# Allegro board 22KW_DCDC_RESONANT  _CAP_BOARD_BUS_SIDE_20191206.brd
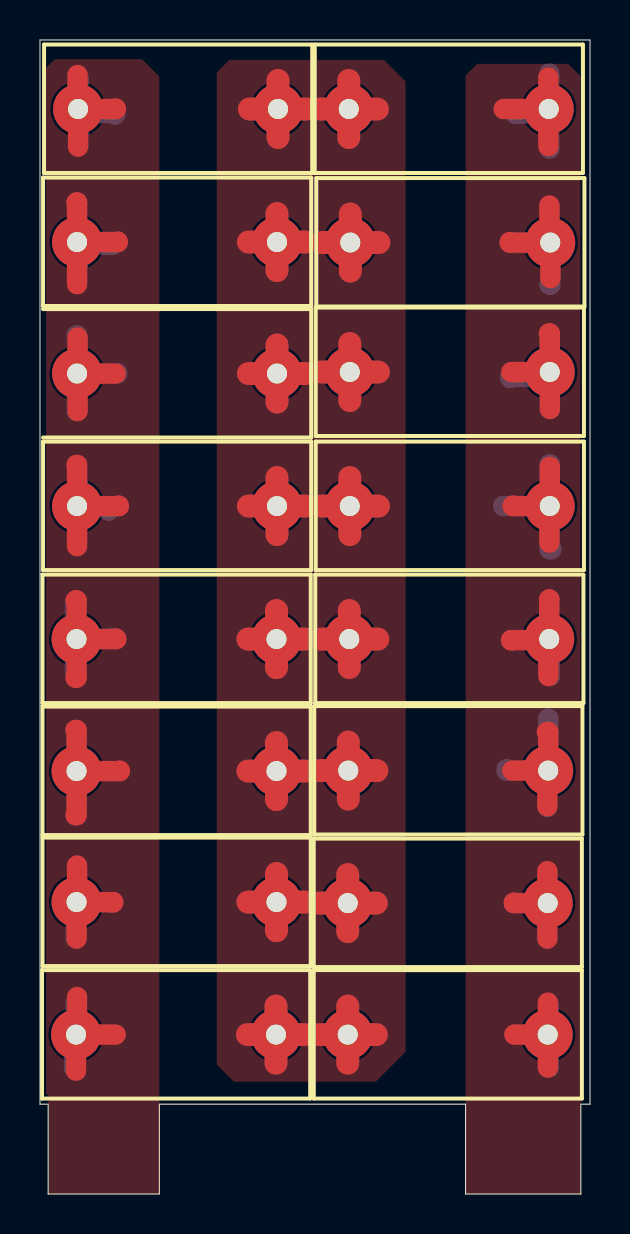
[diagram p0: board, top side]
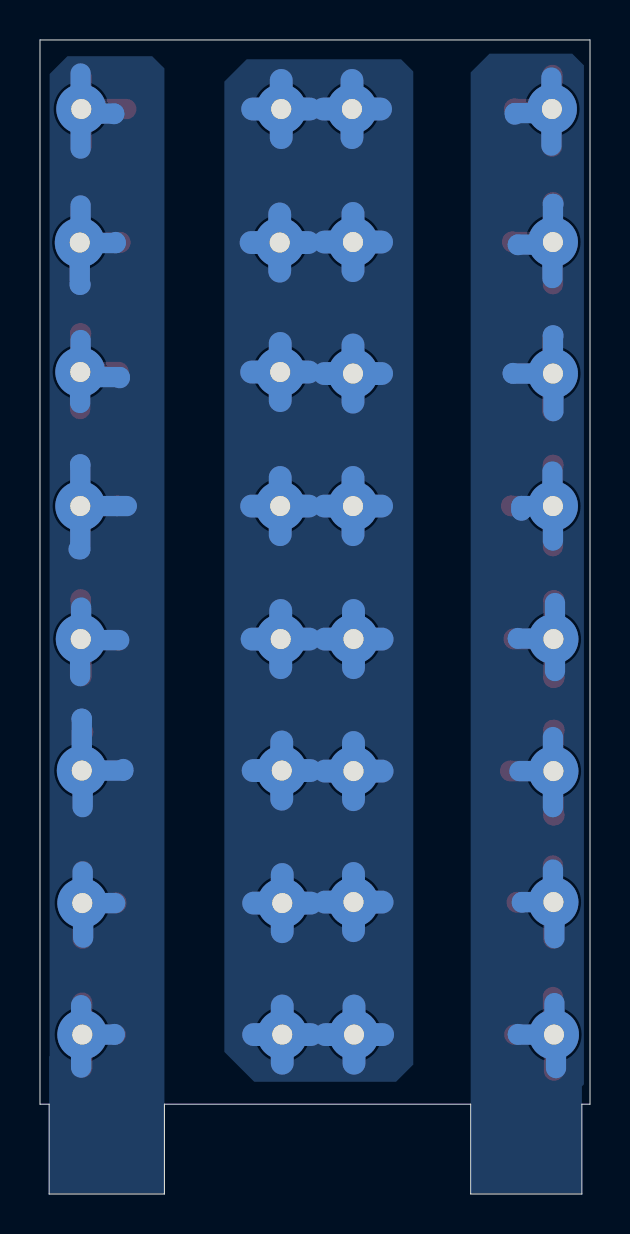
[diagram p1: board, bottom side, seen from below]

Outline 27.51 x 57.73 mm; copper layers: TOP, BOTTOM. Coordinates in mm from the lower left corner of the outline.
Outline path: 0,57.73 27.51,57.73 27.51,4.5 27.05,4.5 27.05,0 21.29,0 21.29,4.5 5.97,4.5 5.97,0 0.41,0 0.41,4.5 0,4.5 0,57.73

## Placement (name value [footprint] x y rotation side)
C1  6.8n  [B32651A7682J000]  1.83 27.76 0 top
C2  6.8n  [B32651A7682J000]  1.8 7.98 0 top
C3  6.8n  [B32651A7682J000]  1.83 14.61 0 top
C4  6.8n  [B32651A7682J000]  1.85 34.42 0 top
C6  6.8n  [B32651A7682J000]  1.85 41.05 0 top
C7  6.8n  [B32651A7682J000]  1.83 21.16 0 top
C8  6.8n  [B32651A7682J000]  1.9 54.28 0 top
C9  6.8n  [B32651A7682J000]  1.85 47.62 0 top
C11  6.8n  [B32651A7682J000]  15.47 27.76 0 top
C12  6.8n  [B32651A7682J000]  15.39 7.98 0 top
C13  6.8n  [B32651A7682J000]  15.39 14.55 0 top
C14  6.8n  [B32651A7682J000]  15.49 34.42 0 top
C16  6.8n  [B32651A7682J000]  15.49 41.12 0 top
C17  6.8n  [B32651A7682J000]  15.42 21.18 0 top
C18  6.8n  [B32651A7682J000]  15.44 54.28 0 top
C19  6.8n  [B32651A7682J000]  15.52 47.6 0 top

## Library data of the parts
C1-C4 C6-C9 C11-C14 C16-C19 = CAP NP

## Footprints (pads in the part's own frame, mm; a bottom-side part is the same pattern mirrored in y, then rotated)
B32651A7682J000
  round 2.5 hole 1: 1(0,0) 2(10,0)

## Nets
N00441: C1.1 C2.1 C3.1 C4.1 C6.1 C7.1 C8.1 C9.1
N03629: C1.2 C2.2 C3.2 C4.2 C6.2 C7.2 C8.2 C9.2 C11.1 C12.1 C13.1 C14.1 C16.1 C17.1 C18.1 C19.1
N03669: C11.2 C12.2 C13.2 C14.2 C16.2 C17.2 C18.2 C19.2

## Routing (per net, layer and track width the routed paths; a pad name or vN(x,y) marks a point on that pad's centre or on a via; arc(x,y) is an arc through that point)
N00441: length 89.8
  TOP w1.016: 1.88,55.98 1.88,54.28 C8.1 ; 1.85,7.98 1.85,9.86 ; 1.85,7.98 C2.1 1.8,6.17 ; 1.85,7.98 3.78,7.98 ; C9.1 3.89,47.62 3.89,47.65 ; C9.1 1.85,49.61 1.83,49.61 ; C9.1 1.85,45.52 ; 1.85,14.61 C3.1 1.83,12.78 ; 1.85,14.61 1.85,16.43 ; 1.85,14.61 3.66,14.61 3.66,14.58 ; 1.83,36.47 1.85,36.47 C4.1 ; C4.1 3.94,34.42 3.94,34.44 ; C4.1 1.85,32.41 ; C1.1 3.81,27.76 3.81,27.79 ; C1.1 1.83,25.83 1.78,25.83 ; C1.1 1.83,29.69 1.78,29.69 ; C8.1 3.78,54.28 3.78,54.31 ; C8.1 1.9,52.4 ; 1.88,41.05 1.88,39.17 ; 1.88,41.05 C6.1 ; 1.88,41.05 3.78,41.05 ; 1.88,41.05 1.88,42.85 ; 3.99,21.18 3.99,21.16 C7.1 ; C7.1 1.83,23.22 1.78,23.22 ; C7.1 1.83,18.95 1.78,18.95
  BOTTOM w1.016: C6.1 1.83,41.05 1.83,39.17 ; C6.1 3.86,41.05 3.86,41.07 ; C6.1 1.85,42.95 1.83,42.95 ; 1.88,34.42 3.43,34.42 3.43,34.19 ; 1.88,34.42 1.88,36.14 ; 1.88,34.42 C4.1 1.85,32.69 ; 3.61,8 3.61,7.98 C2.1 1.78,7.98 ; 1.85,19.35 1.85,21.16 ; 1.85,21.16 1.85,22.86 ; 1.85,21.16 C7.1 ; 1.85,21.16 3.53,21.16 ; 1.75,27.79 3.61,27.79 3.61,27.81 ; 1.75,27.79 1.75,29.57 ; 1.75,27.79 1.75,26.16 ; 1.78,7.98 1.7,7.98 1.7,6.3 ; 1.78,7.98 1.78,9.55 ; 1.93,54.08 1.93,52.45 ; 1.93,54.08 3.76,54.08 3.76,54 ; 1.93,54.08 1.93,54.28 ; C9.1 1.85,49.53 1.83,49.53 ; 1.93,54.28 C8.1 ; 1.93,54.28 1.93,55.85 ; 1.88,45.82 1.88,47.5 3.61,47.5 3.61,47.47 ; 3.4,14.58 3.4,14.61 1.85,14.61 ; 1.85,16.23 1.85,14.61 ; 1.85,14.61 C3.1 1.78,14.61 1.78,12.8
N03629: length 183
  TOP w1.143: 15.52,46.17 C19.1 ; C19.1 14.09,47.6 ; C19.1 15.52,49.03 ; C19.1 16.95,47.6 ; C12.1 15.39,9.41 ; C12.1 13.96,7.98 ; C12.1 15.39,6.55 ; C12.1 16.82,7.98 ; C7.2 13.26,21.16 ; C7.2 10.4,21.16 ; C7.2 11.83,22.59 ; C7.2 11.83,19.73 ; C9.2 13.28,47.62 ; C9.2 10.42,47.62 ; C9.2 11.85,46.2 ; C9.2 11.85,49.05 ; 15.44,52.85 C18.1 ; C18.1 14.01,54.28 ; C18.1 16.87,54.28 ; C18.1 15.44,55.71 ; C1.2 11.83,29.19 ; C1.2 13.26,27.76 ; C1.2 11.83,26.33 ; C1.2 10.4,27.76 ; C8.2 11.9,55.71 ; C8.2 11.9,52.85 ; C8.2 13.33,54.28 ; C8.2 10.48,54.28 ; 15.39,13.12 C13.1 ; C13.1 15.39,15.98 ; C13.1 13.96,14.55 ; C13.1 16.82,14.55 ; C6.2 11.85,42.48 ; C6.2 10.42,41.05 ; C6.2 11.85,39.62 ; C6.2 13.28,41.05 ; C17.1 15.42,22.61 ; C17.1 15.42,19.75 ; C17.1 16.85,21.18 ; C17.1 13.99,21.18 ; 10.4,14.61 C3.2 ; C3.2 13.26,14.61 ; C3.2 11.83,13.18 ; C3.2 11.83,16.03 ; 10.42,34.42 C4.2 ; C4.2 13.28,34.42 ; C4.2 11.85,32.99 ; C4.2 11.85,35.85 ; 14.06,41.12 C16.1 ; C16.1 16.92,41.12 ; C16.1 15.49,39.69 ; C16.1 15.49,42.55 ; C14.1 15.49,35.85 ; C14.1 15.49,32.99 ; C14.1 16.92,34.42 ; C14.1 14.06,34.42 ; 11.8,6.55 C2.2 ; C2.2 13.23,7.98 ; C2.2 11.8,9.41 ; C2.2 10.37,7.98 ; C11.1 16.9,27.76 ; C11.1 14.04,27.76 ; C11.1 15.47,29.19 ; C11.1 15.47,26.33
  BOTTOM w1.143: C4.2 13.28,34.42 ; C4.2 11.85,35.85 ; C4.2 11.85,32.99 ; C4.2 10.42,34.42 ; C14.1 16.92,34.42 ; C14.1 15.49,32.99 ; C14.1 14.06,34.42 ; C14.1 15.49,35.85 ; 10.37,7.98 C2.2 ; C2.2 13.23,7.98 ; C2.2 11.8,6.55 ; C2.2 11.8,9.41 ; 10.48,54.28 C8.2 ; C8.2 13.33,54.28 ; C8.2 11.9,52.85 ; C8.2 11.9,55.71 ; 15.47,26.33 C11.1 ; C11.1 15.47,29.19 ; C11.1 16.9,27.76 ; C11.1 14.04,27.76 ; 13.96,7.98 C12.1 ; C12.1 15.39,9.41 ; C12.1 15.39,6.55 ; C12.1 16.82,7.98 ; 15.44,52.85 C18.1 ; C18.1 15.44,55.71 ; C18.1 16.87,54.28 ; C18.1 14.01,54.28 ; 15.52,46.17 C19.1 ; C19.1 15.52,49.03 ; C19.1 14.09,47.6 ; C19.1 16.95,47.6 ; C7.2 11.83,22.59 ; C7.2 11.83,19.73 ; C7.2 10.4,21.16 ; C7.2 13.26,21.16 ; 11.83,13.18 C3.2 ; C3.2 13.26,14.61 ; C3.2 10.4,14.61 ; C3.2 11.83,16.03 ; 10.4,27.76 C1.2 ; C1.2 11.83,29.19 ; C1.2 11.83,26.33 ; C1.2 13.26,27.76 ; 10.42,41.05 C6.2 ; C6.2 11.85,39.62 ; C6.2 11.85,42.48 ; C6.2 13.28,41.05 ; C16.1 15.49,42.55 ; C16.1 15.49,39.69 ; C16.1 14.06,41.12 ; C16.1 16.92,41.12 ; C13.1 15.39,15.98 ; C13.1 16.82,14.55 ; C13.1 13.96,14.55 ; C13.1 15.39,13.12 ; C17.1 15.42,22.61 ; C17.1 15.42,19.75 ; C17.1 13.99,21.18 ; C17.1 16.85,21.18 ; C9.2 13.28,47.62 ; C9.2 11.85,46.2 ; C9.2 10.42,47.62 ; C9.2 11.85,49.05
N03669: length 89.1
  TOP w1.016: 25.48,29.74 25.47,29.74 C11.2 25.43,27.76 25.43,25.91 ; 25.48,47.6 23.49,47.6 23.49,47.62 ; 25.48,47.6 C19.2 25.53,47.6 25.53,45.82 ; 25.48,47.6 25.48,49.45 ; C16.2 25.5,41.12 25.5,39.27 ; C16.2 23.57,41.12 ; C16.2 25.49,43.05 25.45,43.05 ; 25.37,12.78 25.37,14.55 ; 25.37,14.55 25.37,16.15 ; 25.37,14.55 C13.2 ; 25.37,14.55 23.7,14.55 23.7,14.58 ; 25.48,34.42 23.65,34.42 23.65,34.44 ; 25.48,34.42 C14.2 25.49,36.37 25.5,36.37 ; 25.48,34.42 25.48,32.59 ; 25.4,7.98 C12.2 23.72,7.98 ; 25.4,7.98 25.4,6.32 ; 25.4,7.98 25.4,9.58 ; 25.43,54.28 25.43,52.43 ; 25.43,54.28 C18.2 ; 25.43,54.28 23.19,54.28 ; 25.43,54.28 25.43,55.85 ; 25.35,23.11 25.42,23.11 C17.2 25.37,21.18 ; 25.37,21.18 25.37,19.41 ; 25.37,21.18 23.62,21.18 ; 23.57,27.69 23.57,27.71 25.44,27.71
  BOTTOM w1.016: 25.5,39.57 25.5,41.12 C16.2 ; C14.2 25.49,32.26 25.58,32.26 ; C14.2 25.49,36.5 25.5,36.5 ; C14.2 23.16,34.42 ; 25.35,14.55 25.37,14.55 ; 25.35,14.55 25.35,12.83 ; 25.35,14.55 23.75,14.55 ; 25.37,14.55 25.37,16.13 ; 25.37,14.55 C13.2 ; 25.45,6.32 25.45,7.98 ; 25.45,7.98 C12.2 23.77,7.98 23.77,8 ; 25.45,7.98 25.45,9.45 ; 25.37,21.18 23.34,21.18 23.34,21.26 ; 25.37,21.18 C17.2 25.42,23.77 25.43,23.77 ; 25.37,21.18 25.37,19.35 ; 25.5,25.91 25.5,27.71 25.45,27.71 ; 23.52,40.82 23.52,40.87 25.48,40.87 25.48,42.72 ; 23.55,27.71 25.45,27.71 ; 25.45,27.71 25.45,29.34 ; 23.8,54.03 23.8,54.05 25.48,54.05 25.48,52.3 ; 23.72,47.62 23.72,47.57 25.48,47.57 25.48,49.45 ; 25.48,56.06 25.48,54.28 C18.2 ; 25.48,45.49 25.52,45.49 C19.2

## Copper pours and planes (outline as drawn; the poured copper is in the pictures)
N00441 on TOP: 0.3,5.03 0.41,4.93 0.41,0 5.97,0 5.97,55.91 5.11,56.77 0.74,56.77 0.3,56.34
N00441 on BOTTOM: 0.3,5.49 0.41,5.38 0.41,0 5.97,0 5.97,56.11 5.03,57.05 0.89,57.05 0.3,56.46
N03629 on TOP: 18.29,55.65 18.29,7.11 16.79,5.61 9.7,5.61 8.84,6.48 8.84,56.11 9.42,56.69 9.42,56.74 17.2,56.74
N03629 on BOTTOM: 18.29,55.65 18.29,7.11 16.79,5.61 9.7,5.61 8.84,6.48 8.84,56.16 9.45,56.77 17.17,56.77
N03669 on TOP: 27.03,55.93 27.03,6.91 27.05,6.88 27.05,0 21.29,0 21.29,55.96 21.87,56.54 26.42,56.54
N03669 on BOTTOM: 27.03,6.91 27.05,6.88 27.05,0 21.29,0 21.29,56.31 21.89,56.92 26.14,56.92 27.03,56.03

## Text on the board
User.6: FIGURE | SIZE | 39.37 | DRILL CHART: TOP to BOTTOM | ALL UNITS ARE IN MILS | TOLERANCE | +2.99/-2.99 | PLATED | QTY | 32
